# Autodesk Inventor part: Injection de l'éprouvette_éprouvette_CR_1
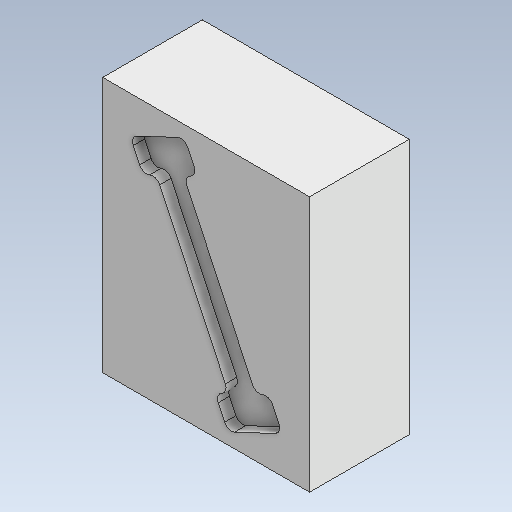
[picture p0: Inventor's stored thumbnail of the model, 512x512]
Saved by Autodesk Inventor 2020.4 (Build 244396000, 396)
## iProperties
Created: 2021-10
Part Number: Injection de l'éprouvette_éprouvette_CR_1
Material: Générique
Document SubType Name: Modeling
Designer: mel
Density: 1 g/cm^3
Appearance: Par défaut
Author: mel
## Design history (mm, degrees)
feature "Sculpter1"
node "Injection de l'éprouvette_éprouvette_CR_Base"
feature "Solide2::Injection de l'éprouvette_éprouvette_CR_Base"
tag "FonctionRepérage2"
node "Solide1"
feature "Surface1"
body "Srf1"
node "Solide2"
feature "Injection de l'éprouvette_éprouvette_CR_Base_Corps"
